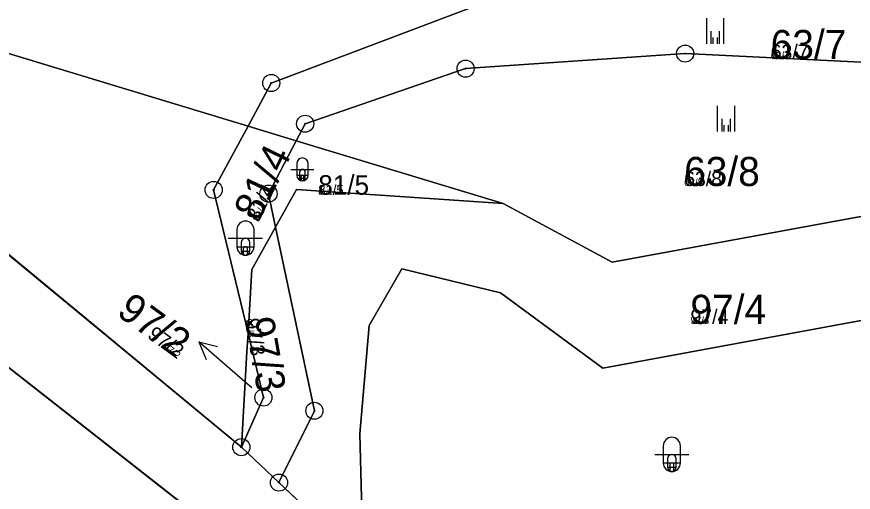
# Model space of a CAD drawing. Extents: x -759873 to -758487, y -975024 to -973516.
# Drawn here: x -759481.95 to -759433.04, y -974202.31 to -974174.51 of the extents above; entities that cross this region are included whole.
import ezdxf

# ---------------------------------------------------------------- set-up
doc = ezdxf.new("R2010")
doc.units = 0
for name, color, linetype in [('KAT_02_hranice parcel', 7, 'Continuous'), ('KAT_03_1000_čísla parcelní', 7, 'Continuous'), ('KAT_03_250_čísla parcelní', 7, 'Continuous'), ('KAT_03_500_čísla parcelní', 7, 'Continuous'), ('KAT_05_1000_značky kultur', 7, 'Continuous'), ('KAT_05_250_značky kultur', 7, 'Continuous'), ('KAT_05_500_značky kultur', 7, 'Continuous'), ('KAT_11_značky bodu BP', 7, 'Continuous'), ('KAT_12_pomocná šipka', 7, 'Continuous'), ('KAT_14_plocha_pozemek', 7, 'Continuous')]:
    doc.layers.add(name, color=color, linetype=linetype)

msp = doc.modelspace()

# ---------------------------------------------------------------- linework, layer by layer
at = {"layer": 'KAT_02_hranice parcel'}
for p, q in [((-759468.82, -974199.68), (-759511.82, -974164.15)), ((-759468.43, -974180.91), (-759465.61, -974181.76)), ((-759465.61, -974181.76), (-759453.51, -974185.43)), ((-759486.83, -974191.58), (-759468.95, -974205.58)), ((-759466.62, -974201.75), (-759468.82, -974199.68)), ((-759461.7, -974206.38), (-759466.62, -974201.75))]:
    msp.add_line(p, q, dxfattribs=at)
for points in [[(-759410.26, -974156.67), (-759405.92, -974141.7), (-759401.27, -974118.23), (-759401.75, -974105.6), (-759398.33, -974098.17), (-759400.83, -974095.4), (-759404.9, -974105.97), (-759404.79, -974118.11), (-759409, -974139.73), (-759414.35, -974156.45), (-759415.35, -974167.22), (-759417.91, -974171.23), (-759427.95, -974173.9), (-759439.19, -974173.13), (-759455.27, -974173.93), (-759467.07, -974178.39), (-759468.43, -974180.91)], [(-759465.61, -974181.76), (-759465.09, -974180.77), (-759455.71, -974177.55), (-759442.87, -974176.67), (-759427.04, -974177.45), (-759416.24, -974174.6), (-759411.97, -974169.1), (-759410.26, -974156.67)], [(-759504.51, -974159.89), (-759486.63, -974175.39), (-759468.43, -974180.91)], [(-759453.51, -974185.43), (-759447.13, -974188.87), (-759429.74, -974185.66), (-759409.87, -974176.03)], [(-759468.43, -974193.02), (-759470.44, -974184.64), (-759468.43, -974180.91)], [(-759466.82, -974186.82), (-759467.23, -974184.86), (-759465.61, -974181.76)], [(-759411.13, -974183.35), (-759430.27, -974191.84), (-759447.69, -974195.05), (-759453.66, -974190.65), (-759459.44, -974189.26), (-759461.34, -974192.57), (-759461.9, -974198.9), (-759461.7, -974206.38)], [(-759466.82, -974186.82), (-759465.59, -974184.62), (-759453.51, -974185.43)], [(-759468.43, -974193.02), (-759468.2, -974189.3), (-759466.82, -974186.82)], [(-759466.62, -974201.75), (-759464.55, -974197.55), (-759466.82, -974186.82)], [(-759468.82, -974199.68), (-759467.53, -974196.78), (-759468.43, -974193.02)], [(-759468.82, -974199.68), (-759468.5, -974194.1), (-759468.43, -974193.02)]]:
    msp.add_lwpolyline(points, dxfattribs=at)
at = {"layer": 'KAT_05_1000_značky kultur'}
for p, q in [((-759441.611, -974176.1), (-759441.611, -974174.6)), ((-759440.61, -974176.1), (-759440.61, -974174.6)), ((-759440.971, -974181.23), (-759440.971, -974179.73)), ((-759439.97, -974181.23), (-759439.97, -974179.73)), ((-759465.585, -974183.105), (-759465.585, -974183.776)), ((-759464.915, -974183.776), (-759464.915, -974183.105)), ((-759465.921, -974183.441), (-759464.579, -974183.441)), ((-759469.081, -974186.961), (-759469.081, -974187.962)), ((-759468.079, -974187.962), (-759468.079, -974186.961)), ((-759469.581, -974187.461), (-759467.579, -974187.461)), ((-759444.151, -974199.601), (-759444.151, -974200.602)), ((-759443.149, -974200.602), (-759443.149, -974199.601)), ((-759444.651, -974200.101), (-759442.649, -974200.101))]:
    msp.add_line(p, q, dxfattribs=at)
for centre, radius, start, end in [((-759465.25, -974183.106), 0.335, 0, 180), ((-759465.25, -974183.776), 0.335, 180, 359.9879), ((-759468.58, -974186.961), 0.5, 0, 180), ((-759468.58, -974187.961), 0.5, 180, 359.9879), ((-759443.65, -974199.601), 0.5, 0, 180), ((-759443.65, -974200.601), 0.5, 180, 359.9879)]:
    msp.add_arc(centre, radius, start, end, dxfattribs=at)
at = {"layer": 'KAT_05_250_značky kultur'}
for p, q in [((-759441.228, -974176.1), (-759441.228, -974175.725)), ((-759440.978, -974176.1), (-759440.978, -974175.725)), ((-759440.588, -974181.23), (-759440.588, -974180.855)), ((-759440.338, -974181.23), (-759440.338, -974180.855)), ((-759465.418, -974183.943), (-759465.082, -974183.943)), ((-759465.334, -974183.859), (-759465.334, -974184.027)), ((-759465.166, -974184.027), (-759465.166, -974183.859)), ((-759468.705, -974188.085), (-759468.705, -974188.336)), ((-759468.455, -974188.336), (-759468.455, -974188.085)), ((-759468.83, -974188.21), (-759468.33, -974188.21)), ((-759443.775, -974200.725), (-759443.775, -974200.976)), ((-759443.525, -974200.976), (-759443.525, -974200.725)), ((-759443.9, -974200.85), (-759443.4, -974200.85))]:
    msp.add_line(p, q, dxfattribs=at)
for centre, radius, start, end in [((-759465.25, -974183.859), 0.0838, 0, 180), ((-759465.25, -974184.026), 0.0838, 180, 359.9879), ((-759468.58, -974188.085), 0.125, 0, 180), ((-759468.58, -974188.335), 0.125, 180, 359.9879), ((-759443.65, -974200.725), 0.125, 0, 180), ((-759443.65, -974200.975), 0.125, 180, 359.9879)]:
    msp.add_arc(centre, radius, start, end, dxfattribs=at)
at = {"layer": 'KAT_05_500_značky kultur'}
for p, q in [((-759441.356, -974176.1), (-759441.356, -974175.35)), ((-759440.855, -974176.1), (-759440.855, -974175.35)), ((-759440.716, -974181.23), (-759440.716, -974180.48)), ((-759440.215, -974181.23), (-759440.215, -974180.48)), ((-759465.417, -974183.608), (-759465.417, -974183.943)), ((-759465.083, -974183.943), (-759465.083, -974183.608)), ((-759465.586, -974183.775), (-759464.915, -974183.775)), ((-759469.081, -974187.961), (-759468.079, -974187.961)), ((-759468.831, -974187.711), (-759468.831, -974188.211)), ((-759468.329, -974188.211), (-759468.329, -974187.711)), ((-759444.15, -974200.601), (-759443.15, -974200.601)), ((-759443.9, -974200.351), (-759443.9, -974200.851)), ((-759443.4, -974200.851), (-759443.4, -974200.351))]:
    msp.add_line(p, q, dxfattribs=at)
for centre, radius, start, end in [((-759465.25, -974183.608), 0.168, 0, 180), ((-759465.25, -974183.943), 0.168, 180, 359.9879), ((-759468.58, -974187.71), 0.25, 0, 180), ((-759468.58, -974188.21), 0.25, 180, 359.9879), ((-759443.65, -974200.35), 0.25, 0, 180), ((-759443.65, -974200.85), 0.25, 180, 359.9879)]:
    msp.add_arc(centre, radius, start, end, dxfattribs=at)
at = {"layer": 'KAT_11_značky bodu BP'}
for centre, radius in [((-759442.87, -974176.67), 0.5), ((-759442.87, -974176.67), 0.0303), ((-759455.71, -974177.55), 0.5), ((-759455.71, -974177.55), 0.0303), ((-759467.07, -974178.39), 0.5), ((-759467.07, -974178.39), 0.0303), ((-759465.09, -974180.77), 0.5), ((-759465.09, -974180.77), 0.0303), ((-759470.44, -974184.64), 0.5), ((-759470.44, -974184.64), 0.0303), ((-759467.23, -974184.86), 0.5), ((-759467.23, -974184.86), 0.0303), ((-759467.53, -974196.78), 0.5), ((-759467.53, -974196.78), 0.0303), ((-759464.55, -974197.55), 0.5), ((-759464.55, -974197.55), 0.0303), ((-759468.82, -974199.68), 0.5), ((-759468.82, -974199.68), 0.0303), ((-759466.62, -974201.75), 0.5), ((-759466.62, -974201.75), 0.0303)]:
    msp.add_circle(centre, radius, dxfattribs=at)
at = {"layer": 'KAT_12_pomocná šipka'}
for p, q in [((-759469.04, -974195.49), (-759471.305, -974193.521)), ((-759471.305, -974193.521), (-759470.221, -974193.8)), ((-759471.305, -974193.521), (-759470.878, -974194.556)), ((-759468.21, -974196.2), (-759469.04, -974195.49))]:
    msp.add_line(p, q, dxfattribs=at)
at = {"layer": 'KAT_14_plocha_pozemek'}
for points in [[(-759593.11, -974016.5), (-759592.85, -974058.75), (-759592.59, -974066.4), (-759592.39, -974072.39), (-759589.64, -974081.94), (-759586.56, -974092.63), (-759585.13, -974095.53), (-759574.33, -974119.77), (-759570.22, -974124.01), (-759564.64, -974129.76), (-759561.39, -974133.11), (-759541.24, -974146.86), (-759540.34, -974147.48), (-759526.16, -974158.85), (-759523.66, -974161.11), (-759516.52, -974167.59), (-759486.83, -974191.58), (-759468.95, -974205.58), (-759465.22, -974208.76), (-759464.16, -974209.67), (-759453.16, -974219.06), (-759423.45, -974241.84)], [(-759428.19, -974233.35), (-759448.25, -974217.2), (-759461.7, -974206.38), (-759466.62, -974201.75), (-759468.82, -974199.68), (-759511.82, -974164.15), (-759531.21, -974148.13), (-759528.87, -974145.44), (-759533.76, -974140.65), (-759536.57, -974142.47), (-759537.72, -974143.21), (-759544.16, -974139.71), (-759568.77, -974119), (-759581.81, -974091.52), (-759587.88, -974071.09), (-759587.42, -974054.22), (-759584.71, -974017.13)], [(-759572.7, -974036.6), (-759569.19, -974051.29), (-759567.32, -974066.36), (-759576.5, -974076.47), (-759552.46, -974113.37), (-759549.68, -974117.63), (-759546.81, -974117.43), (-759536.2, -974132.42), (-759518.38, -974147.87), (-759504.51, -974159.89), (-759486.63, -974175.39), (-759468.43, -974180.91), (-759467.07, -974178.39), (-759455.27, -974173.93), (-759439.19, -974173.13), (-759427.95, -974173.9)]]:
    msp.add_lwpolyline(points, dxfattribs=at)
for points in [[(-759455.71, -974177.55), (-759442.87, -974176.67), (-759427.04, -974177.45), (-759416.24, -974174.6), (-759411.97, -974169.1), (-759410.26, -974156.67), (-759405.92, -974141.7), (-759401.27, -974118.23), (-759401.75, -974105.6), (-759398.33, -974098.17), (-759400.83, -974095.4), (-759404.9, -974105.97), (-759404.79, -974118.11), (-759409, -974139.73), (-759414.35, -974156.45), (-759415.35, -974167.22), (-759417.91, -974171.23), (-759427.95, -974173.9), (-759439.19, -974173.13), (-759455.27, -974173.93), (-759467.07, -974178.39), (-759468.43, -974180.91), (-759465.61, -974181.76), (-759465.09, -974180.77)], [(-759429.74, -974185.66), (-759409.87, -974176.03), (-759409.81, -974176), (-759409.02, -974171.03), (-759410.26, -974156.67), (-759411.97, -974169.1), (-759416.24, -974174.6), (-759427.04, -974177.45), (-759442.87, -974176.67), (-759455.71, -974177.55), (-759465.09, -974180.77), (-759465.61, -974181.76), (-759453.51, -974185.43), (-759447.13, -974188.87)], [(-759468.43, -974193.02), (-759470.44, -974184.64), (-759468.43, -974180.91), (-759486.63, -974175.39), (-759504.51, -974159.89), (-759511.82, -974164.15), (-759468.82, -974199.68), (-759468.5, -974194.1)], [(-759409.87, -974176.03), (-759429.74, -974185.66), (-759447.13, -974188.87), (-759453.51, -974185.43), (-759465.59, -974184.62), (-759466.82, -974186.82), (-759464.55, -974197.55), (-759466.62, -974201.75), (-759461.7, -974206.38), (-759461.9, -974198.9), (-759461.34, -974192.57), (-759459.44, -974189.26), (-759453.66, -974190.65), (-759447.69, -974195.05), (-759430.27, -974191.84), (-759411.13, -974183.35)], [(-759466.82, -974186.82), (-759467.23, -974184.86), (-759465.61, -974181.76), (-759468.43, -974180.91), (-759470.44, -974184.64), (-759468.43, -974193.02), (-759468.2, -974189.3)], [(-759465.59, -974184.62), (-759453.51, -974185.43), (-759465.61, -974181.76), (-759467.23, -974184.86), (-759466.82, -974186.82)], [(-759447.69, -974195.05), (-759453.66, -974190.65), (-759459.44, -974189.26), (-759461.34, -974192.57), (-759461.9, -974198.9), (-759461.7, -974206.38), (-759448.25, -974217.2), (-759441.1, -974209.74), (-759439.36, -974211.8), (-759430.32, -974203.35), (-759421.6, -974198.71), (-759411.55, -974185.84), (-759411.13, -974183.35), (-759430.27, -974191.84)], [(-759464.55, -974197.55), (-759466.82, -974186.82), (-759468.2, -974189.3), (-759468.43, -974193.02), (-759467.53, -974196.78), (-759468.82, -974199.68), (-759466.62, -974201.75)], [(-759468.95, -974205.58), (-759486.83, -974191.58), (-759489.51, -974195.05), (-759488.32, -974198.15), (-759477.26, -974209.24), (-759476.42, -974210.08)], [(-759467.53, -974196.78), (-759468.43, -974193.02), (-759468.5, -974194.1), (-759468.82, -974199.68)]]:
    msp.add_lwpolyline(points, close=True, dxfattribs=at)

# ---------------------------------------------------------------- texts
at = {"layer": 'KAT_03_1000_čísla parcelní'}
for s, height, p in [('63/7', 1.7, (-759437.87, -974176.99)), ('63/8', 1.7, (-759442.93, -974184.41)), ('81/5', 1.14, (-759464.32, -974184.919)), ('97/4', 1.7, (-759442.56, -974192.47))]:
    msp.add_text(s, height=height, dxfattribs=at).set_placement(p)
for s, rotation, p in [('81/4', 64, (-759467.806, -974186.542)), ('97/2', 324, (-759476.185, -974191.913)), ('97/3', 280, (-759468.627, -974192.217))]:
    msp.add_text(s, height=1.7, rotation=rotation, dxfattribs=at).set_placement(p)
at = {"layer": 'KAT_03_250_čísla parcelní'}
for s, height, p in [('63/7', 0.425, (-759437.87, -974176.99)), ('63/8', 0.425, (-759442.93, -974184.41)), ('81/5', 0.285, (-759464.32, -974184.919)), ('97/4', 0.425, (-759442.56, -974192.47))]:
    msp.add_text(s, height=height, dxfattribs=at).set_placement(p)
for s, rotation, p in [('81/4', 64, (-759467.806, -974186.542)), ('97/3', 280, (-759468.627, -974192.217)), ('97/2', 324, (-759473.458, -974193.895))]:
    msp.add_text(s, height=0.425, rotation=rotation, dxfattribs=at).set_placement(p)
at = {"layer": 'KAT_03_500_čísla parcelní'}
for s, height, p in [('63/7', 0.85, (-759437.87, -974176.99)), ('63/8', 0.85, (-759442.93, -974184.41)), ('81/5', 0.57, (-759464.32, -974184.919)), ('97/4', 0.85, (-759442.56, -974192.47))]:
    msp.add_text(s, height=height, dxfattribs=at).set_placement(p)
for s, rotation, p in [('81/4', 64, (-759467.806, -974186.542)), ('97/3', 280, (-759468.627, -974192.217)), ('97/2', 324, (-759474.367, -974193.234))]:
    msp.add_text(s, height=0.85, rotation=rotation, dxfattribs=at).set_placement(p)

doc.saveas('drawing.dxf')
